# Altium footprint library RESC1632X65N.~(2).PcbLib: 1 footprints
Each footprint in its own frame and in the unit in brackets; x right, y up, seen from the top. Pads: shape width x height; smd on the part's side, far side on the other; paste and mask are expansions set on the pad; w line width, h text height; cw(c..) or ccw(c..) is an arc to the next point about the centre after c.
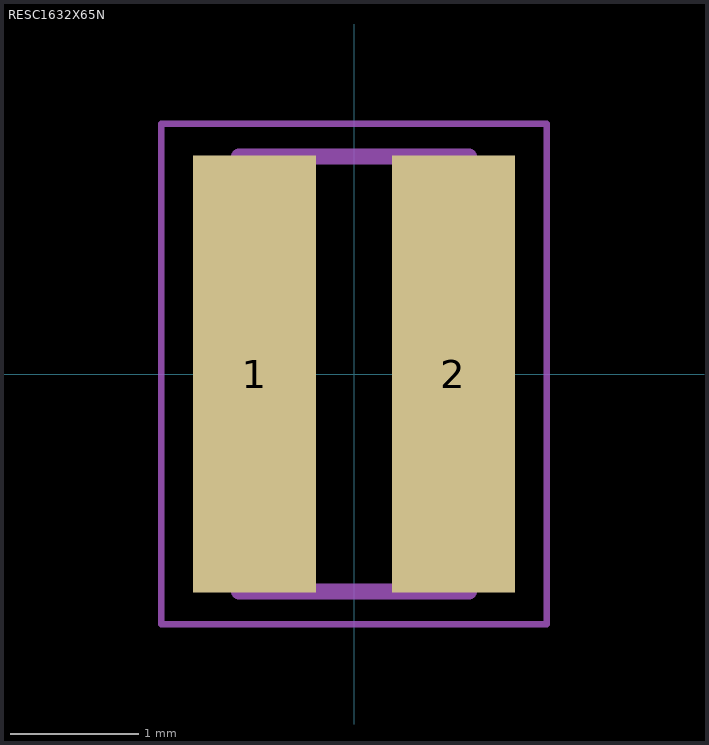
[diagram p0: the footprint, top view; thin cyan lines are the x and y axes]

## RESC1632X65N [mm]
pads (2):
  rect 0.96x3.42 smd: 1(-0.778,0) 2(0.778,0)
Mechanical 13:
  lines w0.127: -0.9,-1.7 -0.9,1.7 0.9,1.7 0.9,-1.7 -0.9,-1.7
Mechanical 15:
  lines w0.05: -1.508,-1.958 -1.508,1.958 1.508,1.958 1.508,-1.958 -1.508,-1.958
